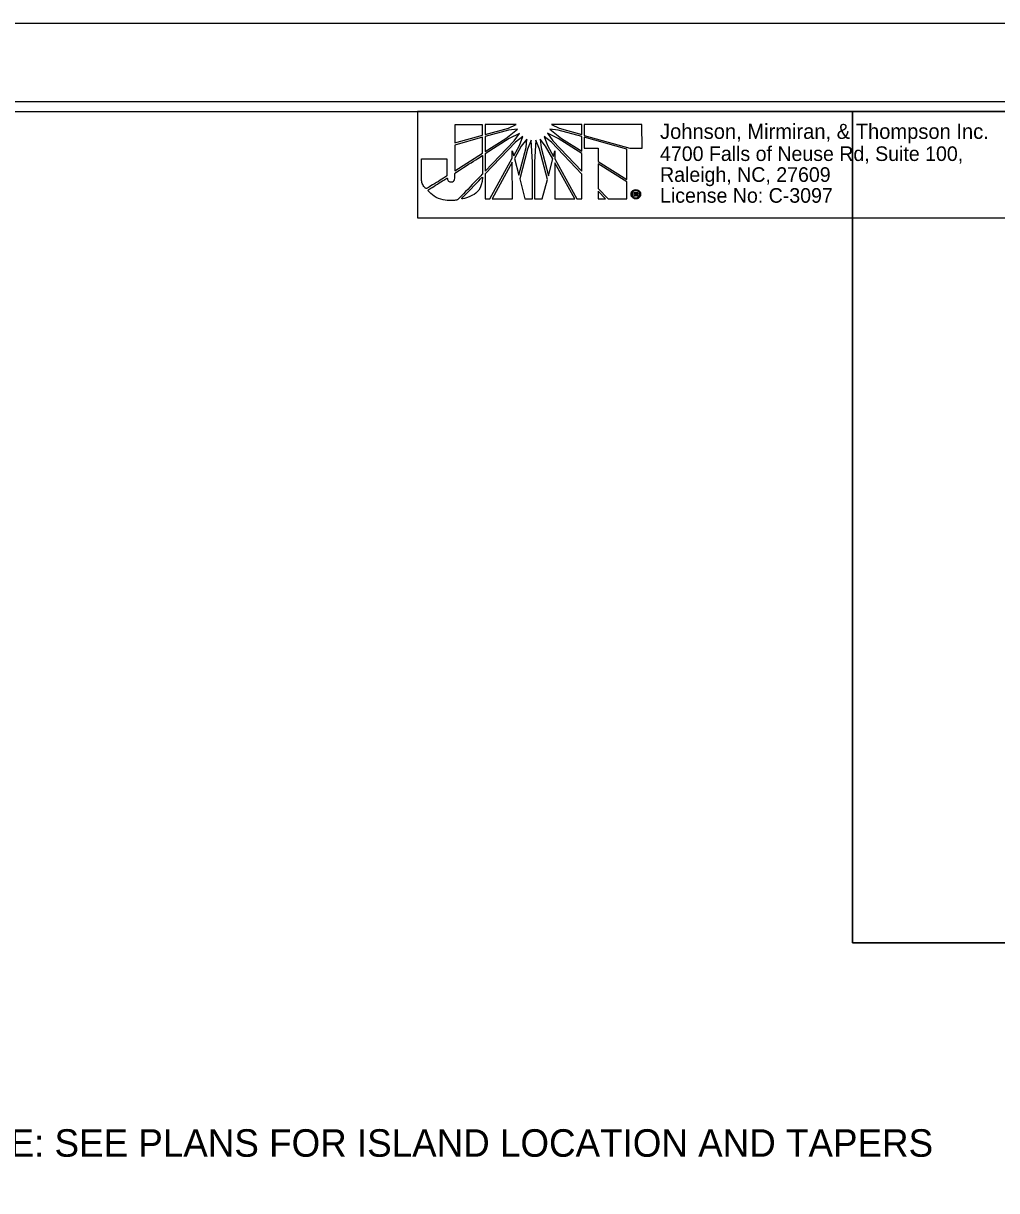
# Model space of a CAD drawing. Extents: x 1640342 to 1730599, y 538663 to 843747.
# Drawn here: x 1730083.9 to 1730133.5, y 539309.4 to 539368.8 of the extents above; entities that cross this region are included whole.
import ezdxf

# ---------------------------------------------------------------- set-up
doc = ezdxf.new("R2010")
doc.units = 0
for name, color, linetype in [('Prop Dimension Text', 7, 'Continuous'), ('Sheet Clip Boundary CELL', 7, 'Continuous'), ('Sheet Layout Plan Border', 7, 'Continuous'), ('Sheet Plan CELL', 7, 'Continuous'), ('Sheet Plan Layout CELL', 7, 'Continuous'), ('Sheet Plot Border Inside CELL', 7, 'Continuous'), ('Sheet Plot Border Outside CELL', 7, 'Continuous'), ('Typical Text Label CELL', 7, 'Continuous')]:
    doc.layers.add(name, color=color, linetype=linetype)

msp = doc.modelspace()

# ---------------------------------------------------------------- linework, layer by layer
at = {"layer": 'Prop Dimension Text'}
for p, q in [((1730107.302, 539363.619), (1730105.899, 539363.617)), ((1730105.899, 539363.617), (1730105.9, 539362.687)), ((1730107.302, 539363.077), (1730107.302, 539363.619)), ((1730109.027, 539363.627), (1730107.448, 539363.626)), ((1730107.448, 539363.626), (1730107.448, 539363.123)), ((1730107.448, 539363.123), (1730108.624, 539363.449)), ((1730108.624, 539363.449), (1730109.027, 539363.627)), ((1730112.37, 539363.624), (1730110.814, 539363.629)), ((1730110.814, 539363.629), (1730111.208, 539363.444)), ((1730111.208, 539363.444), (1730112.37, 539363.119)), ((1730112.37, 539363.119), (1730112.37, 539363.624)), ((1730115.428, 539363.633), (1730112.479, 539363.631)), ((1730112.479, 539363.631), (1730112.479, 539363.089)), ((1730115.43, 539362.425), (1730115.428, 539363.633)), ((1730105.9, 539362.687), (1730107.302, 539363.077)), ((1730107.302, 539362.975), (1730105.9, 539362.58)), ((1730107.303, 539362.162), (1730107.302, 539362.975)), ((1730108.624, 539363.34), (1730107.448, 539363.015)), ((1730107.448, 539363.015), (1730107.449, 539362.255)), ((1730107.449, 539362.255), (1730108.502, 539362.923)), ((1730108.664, 539362.907), (1730107.449, 539362.132)), ((1730108.502, 539362.923), (1730109.082, 539363.396)), ((1730109.082, 539363.396), (1730108.624, 539363.34)), ((1730109.198, 539363.178), (1730108.664, 539362.907)), ((1730108.928, 539362.798), (1730109.198, 539363.178)), ((1730109.361, 539363.009), (1730108.988, 539362.722)), ((1730109.19, 539362.56), (1730109.361, 539363.009)), ((1730109.562, 539362.885), (1730109.285, 539362.528)), ((1730109.523, 539362.452), (1730109.562, 539362.885)), ((1730109.794, 539362.822), (1730109.602, 539362.373)), ((1730109.855, 539361.716), (1730109.794, 539362.822)), ((1730110.025, 539362.823), (1730109.954, 539361.716)), ((1730110.211, 539362.374), (1730110.025, 539362.823)), ((1730110.25, 539362.885), (1730110.296, 539362.436)), ((1730110.521, 539362.529), (1730110.25, 539362.885)), ((1730110.449, 539363.01), (1730110.621, 539362.562)), ((1730110.822, 539362.724), (1730110.449, 539363.01)), ((1730110.613, 539363.18), (1730110.884, 539362.793)), ((1730111.155, 539362.909), (1730110.613, 539363.18)), ((1730110.736, 539363.397), (1730111.324, 539362.916)), ((1730111.169, 539363.342), (1730110.736, 539363.397)), ((1730112.362, 539362.144), (1730111.155, 539362.909)), ((1730112.37, 539363.012), (1730111.169, 539363.342)), ((1730111.324, 539362.916), (1730112.362, 539362.269)), ((1730112.362, 539362.269), (1730112.37, 539363.012)), ((1730112.479, 539363.089), (1730112.479, 539363.073)), ((1730112.479, 539363.073), (1730114.802, 539362.424)), ((1730112.479, 539362.989), (1730112.479, 539362.98)), ((1730114.654, 539362.371), (1730112.479, 539362.989)), ((1730112.479, 539362.98), (1730112.48, 539362.415)), ((1730105.9, 539362.58), (1730105.901, 539361.272)), ((1730107.45, 539361.257), (1730108.928, 539362.798)), ((1730108.988, 539362.722), (1730107.45, 539361.109)), ((1730108.827, 539361.909), (1730108.826, 539362.28)), ((1730108.826, 539362.28), (1730108.896, 539362.025)), ((1730108.896, 539362.025), (1730109.19, 539362.56)), ((1730109.285, 539362.528), (1730108.936, 539361.893)), ((1730109.161, 539361.051), (1730109.523, 539362.452)), ((1730109.602, 539362.373), (1730109.208, 539360.856)), ((1730110.615, 539360.834), (1730110.211, 539362.374)), ((1730110.296, 539362.436), (1730110.661, 539361.02)), ((1730110.885, 539361.872), (1730110.521, 539362.529)), ((1730110.621, 539362.562), (1730110.922, 539362.004)), ((1730112.363, 539361.1), (1730110.822, 539362.724)), ((1730110.884, 539362.793), (1730112.363, 539361.246)), ((1730110.922, 539362.004), (1730110.994, 539362.282)), ((1730110.994, 539362.282), (1730110.994, 539361.872)), ((1730112.48, 539362.415), (1730113.2, 539362.416)), ((1730113.2, 539362.416), (1730113.201, 539361.742)), ((1730114.655, 539360.822), (1730114.654, 539362.371)), ((1730114.802, 539362.424), (1730115.43, 539362.425)), ((1730105.901, 539361.272), (1730107.303, 539362.162)), ((1730107.449, 539362.132), (1730107.45, 539361.257)), ((1730107.683, 539359.836), (1730108.827, 539361.909)), ((1730108.827, 539361.708), (1730107.792, 539359.836)), ((1730108.838, 539359.837), (1730108.827, 539361.708)), ((1730108.936, 539361.893), (1730109.161, 539361.051)), ((1730109.857, 539359.845), (1730109.855, 539361.716)), ((1730109.954, 539361.716), (1730109.956, 539359.845)), ((1730110.661, 539361.02), (1730110.885, 539361.872)), ((1730110.994, 539361.872), (1730112.116, 539359.84)), ((1730112.001, 539359.847), (1730110.994, 539361.67)), ((1730110.994, 539361.67), (1730110.996, 539359.846)), ((1730112.363, 539361.246), (1730112.362, 539362.144)), ((1730113.201, 539361.742), (1730114.655, 539360.822)), ((1730107.45, 539361.109), (1730107.451, 539359.836)), ((1730112.364, 539359.84), (1730112.363, 539361.1)), ((1730113.201, 539361.626), (1730113.202, 539360.371)), ((1730114.655, 539360.713), (1730113.201, 539361.626)), ((1730109.208, 539360.856), (1730109.472, 539359.845)), ((1730110.345, 539359.845), (1730110.615, 539360.834)), ((1730114.656, 539359.843), (1730114.655, 539360.713)), ((1730113.202, 539360.371), (1730113.705, 539359.842)), ((1730113.566, 539359.842), (1730113.202, 539360.235)), ((1730113.202, 539360.235), (1730113.202, 539359.841)), ((1730115.026, 539359.975), (1730115.025, 539360.19)), ((1730115.025, 539360.19), (1730115.113, 539360.19)), ((1730115.074, 539359.975), (1730115.026, 539359.975)), ((1730115.113, 539360.149), (1730115.074, 539360.149)), ((1730115.074, 539360.149), (1730115.074, 539360.098)), ((1730115.074, 539360.098), (1730115.113, 539360.098)), ((1730115.113, 539360.059), (1730115.074, 539360.059)), ((1730115.074, 539360.059), (1730115.074, 539359.975)), ((1730115.113, 539360.317), (1730115.113, 539360.272)), ((1730115.113, 539360.272), (1730115.113, 539360.317)), ((1730115.113, 539360.19), (1730115.113, 539360.149)), ((1730115.113, 539360.149), (1730115.113, 539360.19)), ((1730115.113, 539360.19), (1730115.127, 539360.19)), ((1730115.119, 539360.149), (1730115.113, 539360.149)), ((1730115.113, 539360.098), (1730115.113, 539360.059)), ((1730115.113, 539360.059), (1730115.113, 539360.098)), ((1730115.113, 539360.098), (1730115.115, 539360.098)), ((1730115.115, 539360.059), (1730115.113, 539360.059)), ((1730115.113, 539359.892), (1730115.114, 539359.845)), ((1730115.114, 539359.845), (1730115.113, 539359.892)), ((1730115.113, 539359.892), (1730115.115, 539359.892)), ((1730107.451, 539359.836), (1730107.683, 539359.836)), ((1730107.792, 539359.836), (1730108.838, 539359.837)), ((1730109.472, 539359.845), (1730109.857, 539359.845)), ((1730109.956, 539359.845), (1730110.345, 539359.845)), ((1730110.996, 539359.846), (1730112.001, 539359.847)), ((1730112.116, 539359.84), (1730112.364, 539359.84)), ((1730113.202, 539359.841), (1730113.566, 539359.842)), ((1730113.705, 539359.842), (1730114.656, 539359.843)), ((1730115.115, 539359.845), (1730115.114, 539359.845))]:
    msp.add_line(p, q, dxfattribs=at)
msp.add_lwpolyline([(1730104.001, 539358.871), (1730133.983, 539358.871), (1730133.983, 539364.281), (1730104.001, 539364.281)], close=True, dxfattribs=at)
for points in [[(1730105.9, 539362.687), (1730107.302, 539363.077), (1730107.302, 539363.619), (1730105.899, 539363.617), (1730105.9, 539362.687)], [(1730108.624, 539363.449), (1730109.027, 539363.627), (1730107.448, 539363.626), (1730107.448, 539363.123), (1730108.624, 539363.449)], [(1730111.208, 539363.444), (1730112.37, 539363.119), (1730112.37, 539363.624), (1730110.814, 539363.629), (1730111.208, 539363.444)], [(1730115.428, 539363.633), (1730112.479, 539363.631), (1730112.479, 539363.089), (1730112.479, 539363.073), (1730114.802, 539362.424), (1730115.43, 539362.425), (1730115.428, 539363.633)], [(1730105.901, 539361.272), (1730107.303, 539362.162), (1730107.302, 539362.975), (1730105.9, 539362.58), (1730105.901, 539361.272)], [(1730107.448, 539363.015), (1730107.449, 539362.255), (1730108.502, 539362.923), (1730109.082, 539363.396), (1730108.624, 539363.34), (1730107.448, 539363.015)], [(1730107.449, 539362.132), (1730107.45, 539361.257), (1730108.928, 539362.798), (1730109.198, 539363.178), (1730108.664, 539362.907), (1730107.449, 539362.132)], [(1730109.361, 539363.009), (1730108.988, 539362.722), (1730107.45, 539361.109), (1730107.451, 539359.836), (1730107.683, 539359.836), (1730108.827, 539361.909), (1730108.826, 539362.28), (1730108.896, 539362.025), (1730109.19, 539362.56), (1730109.361, 539363.009)], [(1730109.562, 539362.885), (1730109.285, 539362.528), (1730108.936, 539361.893), (1730109.161, 539361.051), (1730109.523, 539362.452), (1730109.562, 539362.885)], [(1730109.602, 539362.373), (1730109.208, 539360.856), (1730109.472, 539359.845), (1730109.857, 539359.845), (1730109.855, 539361.716), (1730109.794, 539362.822), (1730109.602, 539362.373)], [(1730110.025, 539362.823), (1730109.954, 539361.716), (1730109.956, 539359.845), (1730110.345, 539359.845), (1730110.615, 539360.834), (1730110.211, 539362.374), (1730110.025, 539362.823)], [(1730110.25, 539362.885), (1730110.296, 539362.436), (1730110.661, 539361.02), (1730110.885, 539361.872), (1730110.521, 539362.529), (1730110.25, 539362.885)], [(1730110.449, 539363.01), (1730110.621, 539362.562), (1730110.922, 539362.004), (1730110.994, 539362.282), (1730110.994, 539361.872), (1730112.116, 539359.84), (1730112.364, 539359.84), (1730112.363, 539361.1), (1730110.822, 539362.724), (1730110.449, 539363.01)], [(1730110.613, 539363.18), (1730110.884, 539362.793), (1730112.363, 539361.246), (1730112.362, 539362.144), (1730111.155, 539362.909), (1730110.613, 539363.18)], [(1730110.736, 539363.397), (1730111.324, 539362.916), (1730112.362, 539362.269), (1730112.37, 539363.012), (1730111.169, 539363.342), (1730110.736, 539363.397)], [(1730112.479, 539362.989), (1730112.479, 539362.98), (1730112.48, 539362.415), (1730113.2, 539362.416), (1730113.201, 539361.742), (1730114.655, 539360.822), (1730114.654, 539362.371), (1730112.479, 539362.989)], [(1730107.792, 539359.836), (1730108.838, 539359.837), (1730108.827, 539361.708), (1730107.792, 539359.836)], [(1730110.996, 539359.846), (1730112.001, 539359.847), (1730110.994, 539361.67), (1730110.996, 539359.846)], [(1730113.201, 539361.626), (1730113.202, 539360.371), (1730113.705, 539359.842), (1730114.656, 539359.843), (1730114.655, 539360.713), (1730113.201, 539361.626), (1730113.201, 539361.626)], [(1730113.202, 539359.841), (1730113.202, 539359.841), (1730113.566, 539359.842), (1730113.202, 539360.235), (1730113.202, 539359.841)], [(1730115.207, 539360.026), (1730115.207, 539360.015), (1730115.209, 539360.007), (1730115.209, 539359.999), (1730115.215, 539359.976), (1730115.17, 539359.976)]]:
    msp.add_lwpolyline(points, dxfattribs=at)
for points, degree in [([(1730105.497, 539361.874), (1730105.497, 539361.874), (1730104.199, 539361.872), (1730104.199, 539361.872), (1730104.199, 539361.872), (1730104.199, 539361.06), (1730104.199, 539361.06), (1730104.199, 539361.06), (1730104.199, 539360.974), (1730104.199, 539360.974), (1730104.2, 539360.719), (1730104.283, 539360.518), (1730104.432, 539360.349), (1730104.432, 539360.349), (1730105.498, 539360.998), (1730105.498, 539361.015), (1730105.498, 539361.015), (1730105.497, 539361.874), (1730105.497, 539361.874)], 3), ([(1730105.7, 539360.705), (1730105.617, 539360.704), (1730105.545, 539360.751), (1730105.515, 539360.906), (1730105.515, 539360.906), (1730104.508, 539360.282), (1730104.508, 539360.282), (1730104.819, 539359.956), (1730105.314, 539359.762), (1730105.733, 539359.762), (1730105.842, 539359.762), (1730105.925, 539359.772), (1730106.041, 539359.795), (1730106.041, 539359.795), (1730107.304, 539361.102), (1730107.304, 539361.102), (1730107.304, 539361.102), (1730107.303, 539362.047), (1730107.303, 539362.047), (1730107.303, 539362.047), (1730105.901, 539361.154), (1730105.901, 539361.154), (1730105.901, 539360.8), (1730105.816, 539360.705), (1730105.7, 539360.705)], 3), ([(1730105.7, 539360.705), (1730105.617, 539360.704), (1730105.545, 539360.751), (1730105.515, 539360.906), (1730105.515, 539360.906), (1730104.508, 539360.282), (1730104.508, 539360.282), (1730104.819, 539359.956), (1730105.314, 539359.762), (1730105.733, 539359.762), (1730105.842, 539359.762), (1730105.925, 539359.772), (1730106.041, 539359.795), (1730106.041, 539359.795), (1730107.304, 539361.102), (1730107.304, 539361.102), (1730107.304, 539361.102), (1730107.303, 539362.047), (1730107.303, 539362.047), (1730107.303, 539362.047), (1730105.901, 539361.154), (1730105.901, 539361.154), (1730105.901, 539360.8), (1730105.816, 539360.705), (1730105.7, 539360.705)], 3), ([(1730107.304, 539360.954), (1730107.304, 539360.954), (1730106.212, 539359.825), (1730106.212, 539359.825), (1730106.747, 539359.958), (1730107.279, 539360.312), (1730107.304, 539360.954)], 3), ([(1730115.114, 539359.845), (1730115.049, 539359.845), (1730114.993, 539359.868), (1730114.946, 539359.915), (1730114.899, 539359.96), (1730114.875, 539360.016), (1730114.875, 539360.082), (1730114.875, 539360.149), (1730114.899, 539360.205), (1730114.945, 539360.248), (1730114.992, 539360.293), (1730115.047, 539360.317), (1730115.113, 539360.317)], 3), ([(1730115.113, 539360.272), (1730115.06, 539360.272), (1730115.016, 539360.254), (1730114.979, 539360.219), (1730114.942, 539360.182), (1730114.922, 539360.135), (1730114.922, 539360.083), (1730114.922, 539360.03), (1730114.942, 539359.983), (1730114.979, 539359.946), (1730115.016, 539359.909), (1730115.061, 539359.892), (1730115.113, 539359.892)], 3), ([(1730115.113, 539360.317), (1730115.179, 539360.317), (1730115.236, 539360.293), (1730115.283, 539360.249), (1730115.33, 539360.206), (1730115.353, 539360.149), (1730115.353, 539360.083)], 3), ([(1730115.115, 539359.892), (1730115.168, 539359.892), (1730115.213, 539359.909), (1730115.25, 539359.946), (1730115.287, 539359.983), (1730115.306, 539360.03), (1730115.306, 539360.083), (1730115.306, 539360.136), (1730115.287, 539360.182), (1730115.25, 539360.219), (1730115.213, 539360.254), (1730115.168, 539360.272), (1730115.113, 539360.272)], 3), ([(1730115.115, 539360.098), (1730115.146, 539360.098), (1730115.162, 539360.108), (1730115.162, 539360.126), (1730115.162, 539360.141), (1730115.148, 539360.149), (1730115.119, 539360.149)], 3), ([(1730115.353, 539360.083), (1730115.353, 539360.017), (1730115.33, 539359.96), (1730115.285, 539359.913), (1730115.238, 539359.868), (1730115.182, 539359.845), (1730115.115, 539359.845)], 3), ([(1730115.152, 539360.052), (1730115.146, 539360.055), (1730115.135, 539360.059), (1730115.115, 539360.059)], 2), ([(1730115.127, 539360.19), (1730115.181, 539360.19), (1730115.209, 539360.169), (1730115.209, 539360.126), (1730115.209, 539360.106), (1730115.201, 539360.091), (1730115.184, 539360.079)], 3), ([(1730115.17, 539359.976), (1730115.164, 539359.987), (1730115.16, 539359.999), (1730115.16, 539360.014), (1730115.16, 539360.034), (1730115.158, 539360.046), (1730115.152, 539360.052)], 3), ([(1730115.184, 539360.079), (1730115.197, 539360.071), (1730115.205, 539360.054), (1730115.207, 539360.026)], 2)]:
    msp.add_open_spline(points, degree=degree, dxfattribs=at)
at = {"layer": 'Sheet Clip Boundary CELL'}
msp.add_lwpolyline([(1729883.99, 539154.279), (1730163.993, 539154.279), (1730163.993, 539321.981), (1730126.14, 539321.981), (1730126.14, 539364.279), (1729883.99, 539364.279)], close=True, dxfattribs=at)
at = {"layer": 'Sheet Layout Plan Border'}
msp.add_lwpolyline([(1729883.99, 539154.279), (1730163.993, 539154.279), (1730163.993, 539321.981), (1730126.14, 539321.981), (1730126.14, 539364.279), (1729883.99, 539364.279)], close=True, dxfattribs=at)
at = {"layer": 'Sheet Plan CELL'}
for points in [[(1729873.99, 539154.279), (1729873.985, 539364.274), (1730133.983, 539364.281), (1730133.985, 539334.269), (1730173.993, 539334.266), (1730173.993, 539154.279)], [(1730173.998, 539364.279), (1729873.99, 539364.279), (1729873.99, 539154.279), (1730173.993, 539154.279)]]:
    msp.add_lwpolyline(points, close=True, dxfattribs=at)
at = {"layer": 'Sheet Plan Layout CELL'}
for points in [[(1729873.985, 539364.274), (1729873.99, 539154.279), (1730173.99, 539154.279), (1730173.99, 539321.981), (1730126.14, 539321.981), (1730126.14, 539364.279)], [(1730126.14, 539321.981), (1730173.995, 539321.981), (1730174, 539364.279), (1730126.14, 539364.279)]]:
    msp.add_lwpolyline(points, close=True, dxfattribs=at)
at = {"layer": 'Sheet Plot Border Inside CELL'}
msp.add_lwpolyline([(1729843.293, 539153.776), (1730176.49, 539153.779), (1730176.493, 539364.776), (1729843.293, 539364.776)], close=True, dxfattribs=at)
at = {"layer": 'Sheet Plot Border Outside CELL'}
msp.add_lwpolyline([(1729840.693, 539149.776), (1730177.393, 539149.776), (1730177.393, 539368.776), (1729840.693, 539368.776)], close=True, dxfattribs=at)

# ---------------------------------------------------------------- texts
at = {"layer": 'Prop Dimension Text'}
for s, height, p in [('Johnson, Mirmiran, & Thompson Inc.', 0.76607, (1730116.348, 539362.896)), ('4700 Falls of Neuse Rd, Suite 100, ', 0.74418, (1730116.348, 539361.771)), ('Raleigh, NC, 27609', 0.74418, (1730116.348, 539360.708)), ('License No: C-3097', 0.74418, (1730116.348, 539359.645))]:
    msp.add_text(s, height=height, rotation=360, dxfattribs=at).set_placement(p)
at = {"layer": 'Typical Text Label CELL'}
msp.add_text('NOTE: SEE PLANS FOR ISLAND LOCATION AND TAPERS', height=1.4, dxfattribs=at).set_placement((1730079.277, 539311.089))

doc.saveas('drawing.dxf')
